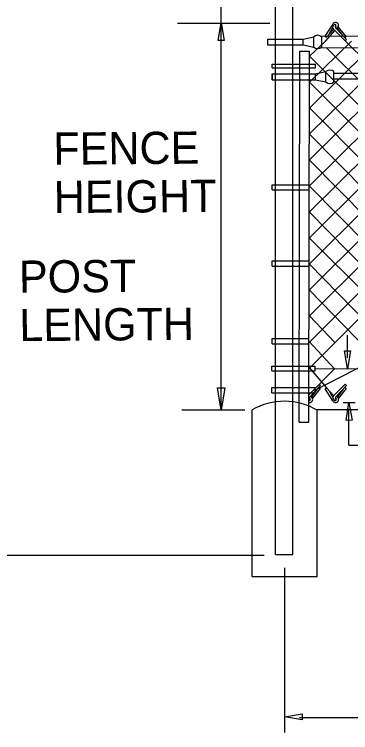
# Model space of a CAD drawing. Extents: x 0 to 2.85, y -0.1 to 1.83.
# Drawn here: x 0.2346 to 0.3391, y 0.706 to 0.9288 of the extents above; entities that cross this region are included whole.
import ezdxf

# ---------------------------------------------------------------- set-up
doc = ezdxf.new("R2010")
doc.units = 0
for name, color, linetype in [('CT_Dimensions', 7, 'Continuous'), ('sb_Chainlink Fence', 7, 'Continuous'), ('sb_Existing Concrete', 7, 'Continuous'), ('sb_Existing Structural Steel', 7, 'Continuous')]:
    doc.layers.add(name, color=color, linetype=linetype)

msp = doc.modelspace()

# ---------------------------------------------------------------- linework, layer by layer
at = {"layer": 'CT_Dimensions'}
for p, q in [((0.29883852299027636, 0.9260819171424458), (0.29879716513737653, 0.9482975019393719)), ((0.28534629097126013, 0.9261039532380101), (0.31398111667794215, 0.9261039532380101)), ((0.29883852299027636, 0.8061928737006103), (0.29883852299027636, 0.9260819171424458)), ((0.3380311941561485, 0.8223121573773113), (0.3380311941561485, 0.8292597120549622)), ((0.3367005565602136, 0.8083953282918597), (0.3404589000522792, 0.8083953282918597)), ((0.3384804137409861, 0.7951406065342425), (0.3384804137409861, 0.806449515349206)), ((0.2866145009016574, 0.8061928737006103), (0.3062139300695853, 0.8061928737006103)), ((0.3384804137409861, 0.7951406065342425), (0.3435078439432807, 0.7951406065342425)), ((0.22463583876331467, 0.7610906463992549), (0.3122171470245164, 0.7610906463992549)), ((0.3185105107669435, 0.757163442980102), (0.3185105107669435, 0.7060321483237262)), ((0.3231760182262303, 0.7107763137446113), (0.7067152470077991, 0.7107763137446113))]:
    msp.add_line(p, q, dxfattribs=at)
for points in [[(0.297908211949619, 0.9206600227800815), (0.29882430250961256, 0.9261565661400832), (0.29974039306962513, 0.9206600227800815)], [(0.3389721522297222, 0.8244522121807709), (0.33805606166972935, 0.8189556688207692), (0.33713997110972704, 0.8244522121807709)], [(0.2999841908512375, 0.8129497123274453), (0.2988410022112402, 0.8060905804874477), (0.297697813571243, 0.8129497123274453)], [(0.3376468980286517, 0.8028770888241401), (0.33847912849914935, 0.8083869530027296), (0.3394788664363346, 0.80290500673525)], [(0.32398169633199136, 0.7100038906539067), (0.3184851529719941, 0.7109199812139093), (0.32398169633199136, 0.7118360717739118)]]:
    msp.add_lwpolyline(points, close=True, dxfattribs=at)
at = {"layer": 'sb_Chainlink Fence'}
for p, q in [((0.33352864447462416, 0.9257579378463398), (0.33109216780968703, 0.9220690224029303)), ((0.33357623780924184, 0.925089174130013), (0.3340213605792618, 0.925616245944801)), ((0.3339802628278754, 0.9255729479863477), (0.33357623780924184, 0.925089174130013)), ((0.33450236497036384, 0.9252874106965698), (0.334338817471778, 0.9249331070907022)), ((0.3343394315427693, 0.9249456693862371), (0.3345020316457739, 0.92527937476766)), ((0.334685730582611, 0.9242981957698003), (0.33518094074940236, 0.9248844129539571)), ((0.33469229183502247, 0.9243071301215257), (0.33518343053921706, 0.9248864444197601)), ((0.33660266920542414, 0.9222251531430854), (0.3349056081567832, 0.9245351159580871)), ((0.33518094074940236, 0.9248844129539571), (0.3352173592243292, 0.9249524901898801)), ((0.3352173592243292, 0.9249524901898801), (0.33524839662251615, 0.9250253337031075)), ((0.3376416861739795, 0.9218930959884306), (0.3352288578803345, 0.9249278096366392)), ((0.33123622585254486, 0.9204814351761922), (0.3342715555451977, 0.9238990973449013)), ((0.3315381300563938, 0.9217643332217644), (0.3337079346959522, 0.9241017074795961)), ((0.3315381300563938, 0.9217643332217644), (0.333694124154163, 0.9240879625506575)), ((0.33325127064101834, 0.9243024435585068), (0.33243962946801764, 0.922750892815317)), ((0.3337528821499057, 0.9242512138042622), (0.3373802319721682, 0.9206084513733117)), ((0.3345505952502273, 0.9243937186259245), (0.3377760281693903, 0.9209671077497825)), ((0.32614401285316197, 0.819003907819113), (0.4279029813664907, 0.9204390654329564)), ((0.32615363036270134, 0.8270745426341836), (0.4198495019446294, 0.9204594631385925)), ((0.3261632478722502, 0.8351451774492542), (0.41177140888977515, 0.9205071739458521)), ((0.3261728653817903, 0.8432158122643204), (0.40371853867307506, 0.9205128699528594)), ((0.32618248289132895, 0.851286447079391), (0.39566180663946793, 0.9205576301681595)), ((0.32619210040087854, 0.8593570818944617), (0.38759939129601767, 0.9204980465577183)), ((0.3262017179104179, 0.8674277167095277), (0.379545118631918, 0.9204814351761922)), ((0.326211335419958, 0.8754983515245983), (0.37149163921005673, 0.9205018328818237)), ((0.32622095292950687, 0.883568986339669), (0.3634625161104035, 0.9205071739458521)), ((0.3262305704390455, 0.8916396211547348), (0.35540964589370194, 0.9205128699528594)), ((0.3262401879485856, 0.8997102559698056), (0.34735291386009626, 0.9205576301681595)), ((0.3262498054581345, 0.9077808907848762), (0.3392904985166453, 0.9204980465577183)), ((0.32625942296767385, 0.9158515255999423), (0.33123622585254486, 0.9204814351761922)), ((0.3376416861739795, 0.9218930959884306), (0.33724588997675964, 0.9215344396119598)), ((0.3377760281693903, 0.9209671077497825), (0.3373802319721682, 0.9206084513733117)), ((0.3373802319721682, 0.9206084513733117), (0.44404641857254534, 0.8141771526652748)), ((0.33146522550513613, 0.9184956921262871), (0.4359840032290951, 0.8142367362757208)), ((0.3262594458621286, 0.9158707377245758), (0.428892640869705, 0.8132736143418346)), ((0.326249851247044, 0.9078193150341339), (0.4213939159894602, 0.812524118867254)), ((0.3262402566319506, 0.8997678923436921), (0.4117981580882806, 0.8141852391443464)), ((0.32623066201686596, 0.8917164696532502), (0.404047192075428, 0.8128966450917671)), ((0.3262210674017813, 0.8836650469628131), (0.39599046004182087, 0.8128518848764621)), ((0.32621147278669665, 0.8756136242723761), (0.3879280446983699, 0.8129114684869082)), ((0.32620187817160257, 0.8675622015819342), (0.3798737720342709, 0.8129280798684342)), ((0.3261922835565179, 0.8595107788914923), (0.37151838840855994, 0.814190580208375)), ((0.326182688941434, 0.8514593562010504), (0.3637911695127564, 0.8129023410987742)), ((0.32617309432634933, 0.8434079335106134), (0.3557382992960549, 0.8128966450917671)), ((0.32616349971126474, 0.8353565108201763), (0.33416196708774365, 0.8269913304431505)), ((0.32615390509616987, 0.8273050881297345), (0.33401311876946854, 0.8189040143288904)), ((0.3261343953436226, 0.810933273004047), (0.33403338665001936, 0.8188106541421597)), ((0.3261443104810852, 0.8192536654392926), (0.3315648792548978, 0.8129280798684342)), ((0.32612665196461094, 0.8108230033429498), (0.32935350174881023, 0.8140635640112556)), ((0.3265238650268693, 0.8102782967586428), (0.3297492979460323, 0.8137049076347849)), ((0.32961495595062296, 0.8127789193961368), (0.3292191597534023, 0.8131375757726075)), ((0.3297492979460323, 0.8137049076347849), (0.32935350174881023, 0.8140635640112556)), ((0.3337796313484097, 0.8104411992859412), (0.3374069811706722, 0.8140839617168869)), ((0.33457734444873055, 0.8102986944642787), (0.33780277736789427, 0.8137253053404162)), ((0.3376684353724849, 0.8127993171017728), (0.3372726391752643, 0.8131579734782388)), ((0.33780277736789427, 0.8137253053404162), (0.3374069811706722, 0.8140839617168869)), ((0.32857593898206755, 0.8124468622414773), (0.3268788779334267, 0.8101368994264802)), ((0.32961495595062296, 0.8127789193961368), (0.3272021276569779, 0.809744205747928)), ((0.331118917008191, 0.8126233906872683), (0.3315648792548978, 0.8129280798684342)), ((0.3335553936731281, 0.8089344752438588), (0.331118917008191, 0.8126233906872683)), ((0.3315648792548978, 0.8129280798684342), (0.33372087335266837, 0.8106044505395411)), ((0.3315648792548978, 0.8129280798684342), (0.33373468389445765, 0.8105907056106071)), ((0.333278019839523, 0.810389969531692), (0.33246637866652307, 0.8119415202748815)), ((0.33662941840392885, 0.8124672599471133), (0.33493235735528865, 0.8101572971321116)), ((0.3376684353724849, 0.8127993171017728), (0.3352556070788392, 0.8097646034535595)), ((0.3264756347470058, 0.8093846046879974), (0.32631208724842, 0.8097389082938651)), ((0.3263127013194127, 0.8097263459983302), (0.32647530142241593, 0.8093926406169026)), ((0.3266590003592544, 0.810373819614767), (0.32715421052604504, 0.8097876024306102)), ((0.32719062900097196, 0.8097195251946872), (0.3272216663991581, 0.8096466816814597)), ((0.33400701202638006, 0.809119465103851), (0.3336029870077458, 0.8096032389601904)), ((0.3336029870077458, 0.8096032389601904), (0.3340481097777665, 0.8090761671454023)), ((0.33452911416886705, 0.8094050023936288), (0.33436556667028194, 0.8097593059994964)), ((0.3343661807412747, 0.8097467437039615), (0.3345287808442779, 0.8094130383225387)), ((0.3347124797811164, 0.8103942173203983), (0.335207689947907, 0.8098080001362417)), ((0.3347190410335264, 0.8103852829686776), (0.3352101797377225, 0.8098059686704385)), ((0.335207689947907, 0.8098080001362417), (0.3352441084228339, 0.8097399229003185)), ((0.3352441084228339, 0.8097399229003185), (0.3352751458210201, 0.8096670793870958)), ((0.32835194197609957, 0.8062680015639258), (0.7544498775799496, 0.8058717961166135))]:
    msp.add_line(p, q, dxfattribs=at)
for centre, radius, start, end in [((0.33350324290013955, 0.9242583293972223), 0.00025580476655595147, 319.02146199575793, 170.0695590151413), ((0.3338356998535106, 0.9248058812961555), 0.0003843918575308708, 140.20166010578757, 233.0052527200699), ((0.33384620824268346, 0.9248063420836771), 0.0003909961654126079, 133.66718540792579, 232.2343578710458), ((0.33436709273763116, 0.925343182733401), 0.0009354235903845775, 330.7731305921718, 153.67978342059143), ((0.33421307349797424, 0.9253785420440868), 0.00030330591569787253, 342.5147558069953, 140.13680881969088), ((0.33421416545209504, 0.9253799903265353), 0.00030494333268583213, 340.73435754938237, 129.21739859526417), ((0.3347265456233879, 0.924773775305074), 0.00041880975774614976, 156.48328493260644, 245.15783350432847), ((0.32618634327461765, 0.8092934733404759), 0.00030330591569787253, 263.73208707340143, 17.48524419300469), ((0.3263403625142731, 0.8093288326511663), 0.0009354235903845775, 260.2979182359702, 29.22686940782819), ((0.3266998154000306, 0.8098982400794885), 0.00041880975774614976, 114.84216649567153, 203.51671506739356), ((0.32618743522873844, 0.8092920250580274), 0.00030494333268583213, 302.84788744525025, 19.265642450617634), ((0.3335299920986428, 0.8104340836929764), 0.00025580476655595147, 189.9304409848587, 40.97853800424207), ((0.3338624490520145, 0.8098865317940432), 0.0003843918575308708, 126.9947472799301, 219.79833989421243), ((0.33387295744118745, 0.8098860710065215), 0.0003909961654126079, 127.7656421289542, 226.33281459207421), ((0.33439384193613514, 0.8093492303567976), 0.0009354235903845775, 206.32021657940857, 29.22686940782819), ((0.33423982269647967, 0.8093138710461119), 0.00030330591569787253, 219.86319118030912, 17.48524419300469), ((0.3342409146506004, 0.8093124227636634), 0.00030494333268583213, 230.78260140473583, 19.265642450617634), ((0.3347532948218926, 0.8099186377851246), 0.00041880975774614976, 114.84216649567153, 203.51671506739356)]:
    msp.add_arc(centre, radius, start, end, dxfattribs=at)
at = {"layer": 'sb_Existing Concrete'}
for p, q in [((0.308450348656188, 0.7544999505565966), (0.3084414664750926, 0.8061261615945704)), ((0.3286605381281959, 0.7544999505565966), (0.3286508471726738, 0.8060627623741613)), ((0.308450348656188, 0.7544999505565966), (0.3286605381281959, 0.7544999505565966))]:
    msp.add_line(p, q, dxfattribs=at)
msp.add_arc((0.3184909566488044, 0.7884986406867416), 0.020290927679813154, 59.952950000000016, 119.6875638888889, dxfattribs=at)
at = {"layer": 'sb_Existing Structural Steel'}
for p, q in [((0.31574716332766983, 0.8087145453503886), (0.31574716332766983, 0.9317274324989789)), ((0.32109012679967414, 0.8086073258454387), (0.32109012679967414, 0.9317672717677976)), ((0.32972619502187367, 0.922068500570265), (0.7463728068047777, 0.9233474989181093)), ((0.31337977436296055, 0.9211504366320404), (0.3243344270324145, 0.9211504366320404)), ((0.3133960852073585, 0.9192872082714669), (0.3133960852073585, 0.9211313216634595)), ((0.3243344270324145, 0.9211504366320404), (0.32760925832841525, 0.9218040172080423)), ((0.3243344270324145, 0.9193063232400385), (0.3243344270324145, 0.9211504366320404)), ((0.32760925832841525, 0.918651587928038), (0.32760925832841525, 0.9218040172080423)), ((0.33008501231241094, 0.918651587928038), (0.33008501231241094, 0.9218040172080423)), ((0.33109216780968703, 0.9220690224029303), (0.3315381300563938, 0.9217643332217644)), ((0.31337977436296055, 0.9193063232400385), (0.3243344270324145, 0.9193063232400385)), ((0.3243344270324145, 0.9193063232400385), (0.32760925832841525, 0.918651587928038)), ((0.3297730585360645, 0.9184370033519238), (0.7393045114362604, 0.9196941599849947)), ((0.32310052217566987, 0.8023683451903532), (0.3232761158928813, 0.9173403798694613)), ((0.3232761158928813, 0.9173403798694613), (0.32629228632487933, 0.9173403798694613)), ((0.3261166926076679, 0.8023683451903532), (0.32629228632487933, 0.9173403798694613)), ((0.3146940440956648, 0.9133364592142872), (0.32810283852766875, 0.9133364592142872)), ((0.3146940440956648, 0.9122232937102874), (0.3146940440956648, 0.9133364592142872)), ((0.32810283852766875, 0.9122232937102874), (0.32810283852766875, 0.9133364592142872)), ((0.3146940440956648, 0.9122232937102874), (0.32810283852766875, 0.9122232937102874)), ((0.3146940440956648, 0.9103768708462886), (0.32810283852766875, 0.9103768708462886)), ((0.3146940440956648, 0.9085327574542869), (0.3146940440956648, 0.9103768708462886)), ((0.3146940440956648, 0.9103768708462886), (0.3146940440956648, 0.9085327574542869)), ((0.32810283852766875, 0.9103768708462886), (0.33137882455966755, 0.911031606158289)), ((0.32810283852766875, 0.9085327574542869), (0.32810283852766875, 0.9103768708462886)), ((0.33137882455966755, 0.9078780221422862), (0.33137882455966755, 0.911031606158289)), ((0.503196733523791, 0.9104170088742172), (0.33383277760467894, 0.910482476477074)), ((0.3338545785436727, 0.9078780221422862), (0.3338545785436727, 0.911031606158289)), ((0.3146940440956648, 0.9085327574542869), (0.32810283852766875, 0.9085327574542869)), ((0.32810283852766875, 0.9085327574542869), (0.33137882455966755, 0.9078780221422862)), ((0.5031960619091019, 0.9086795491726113), (0.3338321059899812, 0.9087450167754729)), ((0.3146940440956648, 0.8743823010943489), (0.3146940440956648, 0.8758811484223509)), ((0.3146940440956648, 0.8758811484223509), (0.3261524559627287, 0.8758811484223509)), ((0.3146940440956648, 0.8743823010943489), (0.326179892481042, 0.8743823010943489)), ((0.41481047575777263, 0.8564575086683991), (0.3280207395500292, 0.8122561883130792)), ((0.3146940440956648, 0.8507437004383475), (0.3146940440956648, 0.8523568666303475)), ((0.3146940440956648, 0.8523568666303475), (0.3261531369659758, 0.8523568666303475)), ((0.3146940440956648, 0.8507437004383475), (0.3261970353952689, 0.8507437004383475)), ((0.3146940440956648, 0.8265646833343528), (0.3146940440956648, 0.8282575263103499)), ((0.3146940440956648, 0.8282575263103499), (0.3261786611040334, 0.8282575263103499)), ((0.3146940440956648, 0.8265646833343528), (0.3261347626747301, 0.8265646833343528)), ((0.31461780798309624, 0.8196652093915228), (0.3280266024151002, 0.8196652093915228)), ((0.31461780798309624, 0.8182056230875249), (0.31461780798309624, 0.8196652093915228)), ((0.31461780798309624, 0.8182056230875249), (0.3280266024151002, 0.8182056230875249)), ((0.3279582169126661, 0.8189246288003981), (1.0977552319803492, 0.8177376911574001)), ((0.3280266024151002, 0.8182056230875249), (0.3280266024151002, 0.8196652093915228)), ((0.32320949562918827, 0.814190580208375), (0.32320949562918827, 0.814190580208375)), ((0.3145879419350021, 0.8130883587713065), (0.32799673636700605, 0.8130883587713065)), ((0.3145879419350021, 0.8113978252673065), (0.3145879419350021, 0.8130883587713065)), ((0.3145879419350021, 0.8113978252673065), (0.32799673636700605, 0.8113978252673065)), ((0.32799673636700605, 0.8113978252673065), (0.3279742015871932, 0.8114120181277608)), ((0.32799673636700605, 0.8113978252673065), (0.32799673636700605, 0.8130883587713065)), ((0.3157401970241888, 0.7612909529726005), (0.3157401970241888, 0.8086130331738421)), ((0.3210831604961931, 0.7612909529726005), (0.3210831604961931, 0.8086130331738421)), ((0.32310052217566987, 0.8023683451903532), (0.3261166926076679, 0.8023683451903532)), ((0.3157401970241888, 0.7612909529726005), (0.3210831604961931, 0.7612909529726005))]:
    msp.add_line(p, q, dxfattribs=at)
for centre, radius, start, end in [((0.3288472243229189, 0.9204949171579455), 0.0018019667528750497, 46.614302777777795, 133.38569444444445), ((0.3288472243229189, 0.9199612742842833), 0.0018019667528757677, 226.61430555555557, 313.38569722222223), ((0.3326162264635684, 0.9097215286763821), 0.0018019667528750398, 46.614302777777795, 133.38569444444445), ((0.3326162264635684, 0.9091878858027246), 0.0018019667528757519, 226.61430555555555, 313.38569722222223)]:
    msp.add_arc(centre, radius, start, end, dxfattribs=at)

# ---------------------------------------------------------------- texts
at = {"layer": 'CT_Dimensions'}
for s, p in [('FENCE ', (0.2467817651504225, 0.8821511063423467)), ('HEIGHT', (0.2468931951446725, 0.8671515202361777)), ('POST', (0.23610714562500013, 0.8424393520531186)), ('LENGTH', (0.23621857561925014, 0.8274397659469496))]:
    msp.add_text(s, height=0.01, rotation=0.4256351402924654, dxfattribs=at).set_placement(p)

doc.saveas('drawing.dxf')
